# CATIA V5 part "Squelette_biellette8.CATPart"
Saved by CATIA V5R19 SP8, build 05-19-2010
Part number: Squelette_biellette8
Bounding box of the stored display mesh (mm): x 0 to 20, y 10 to 10, z 10 to 64.364
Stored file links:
  G:\EU_thinkMotion\CFAO_2010\MMS_groupe2\MMS_groupe2\A reprendre\jcauchy\Squelette_biellette8.CATPart
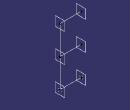
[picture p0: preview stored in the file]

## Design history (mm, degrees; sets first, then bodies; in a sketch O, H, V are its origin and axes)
Parameters
  Longueurbiellette_biellette8 = 27.182 mm
  Longueurfixation_biellette8 = 20 mm
Set1
  Point1: (20 {= Longueurfixation_biellette8}, 10, 10)
  Point2: (0, 10, 10)
  Line1: type PtPt, FirstPoint Point1, SecondPoint Point2
  Point3: type OnCurve, Support Line1, RefPoint Point2, Length -20 {= -Longueurfixation_biellette8}
  Plane1: type Normal, Curve Line1, RefPoint Point2
  Plane2: type Normal, Curve Line1, RefPoint Point1
  Line2: type Angle, RefPoint Point3, Curve Line1, Support zx-plane, Start 0, End 27.182 {= Longueurbiellette_biellette8}, Angle 90
  Line3: type Normal, RefPoint vertex of Line2, RefSkin Plane1, Start 0, End 20 {= Longueurfixation_biellette8}
  Plane3: type Normal, Curve Line3, RefPoint vertex of Line3
  Plane4: type Normal, Curve Line3, RefPoint vertex of Line3
  Line4: type PtDir, RefPoint vertex of Line2, Direction Line2, Start 0, End 27.182 {= Longueurbiellette_biellette8}
  Line5: type PtDir, RefPoint vertex of Line4, Direction Line1, Start 0, End 20 {= Longueurfixation_biellette8}
  Plane5: type Normal, Curve Line5, RefPoint vertex of Line5
  Plane6: type Normal, Curve Line5, RefPoint vertex of Line5
Body1 (main body)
